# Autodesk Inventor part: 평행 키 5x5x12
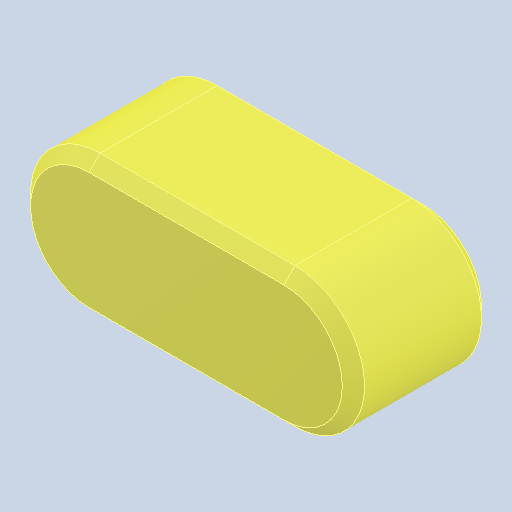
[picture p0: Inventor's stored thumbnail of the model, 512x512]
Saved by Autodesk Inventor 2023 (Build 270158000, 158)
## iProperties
Created: 2025-03
Part Number: 평행 키 5x5x12
Material: 강철, 연강
Description: 키 및 해당 키홈
Document SubType Name: Modeling
Designer: User
Density: 7.85 g/cm^3
Appearance: 기본값
Author: jhkim
Sending System: Autodesk Inventor 2025
Preprocessor: ST-DEVELOPER v20
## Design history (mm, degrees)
feature "Solid1"
node "솔리드1"
